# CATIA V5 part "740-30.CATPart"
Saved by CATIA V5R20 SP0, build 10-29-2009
Part number: 740-30
Bounding box of the stored display mesh (mm): x -27.9 to 27.9, y -26 to 27.9, z -30 to 12
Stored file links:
  C:\Users\Utente\Desktop\IO LAVORO\3D X SITO CF\X SITO\740\740-30.CATPart
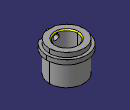
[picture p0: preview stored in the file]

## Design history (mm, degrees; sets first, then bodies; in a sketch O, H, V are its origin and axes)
Set1
  DatumSurface1 to DatumSurface35 "740-30"
Body1 (main body)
